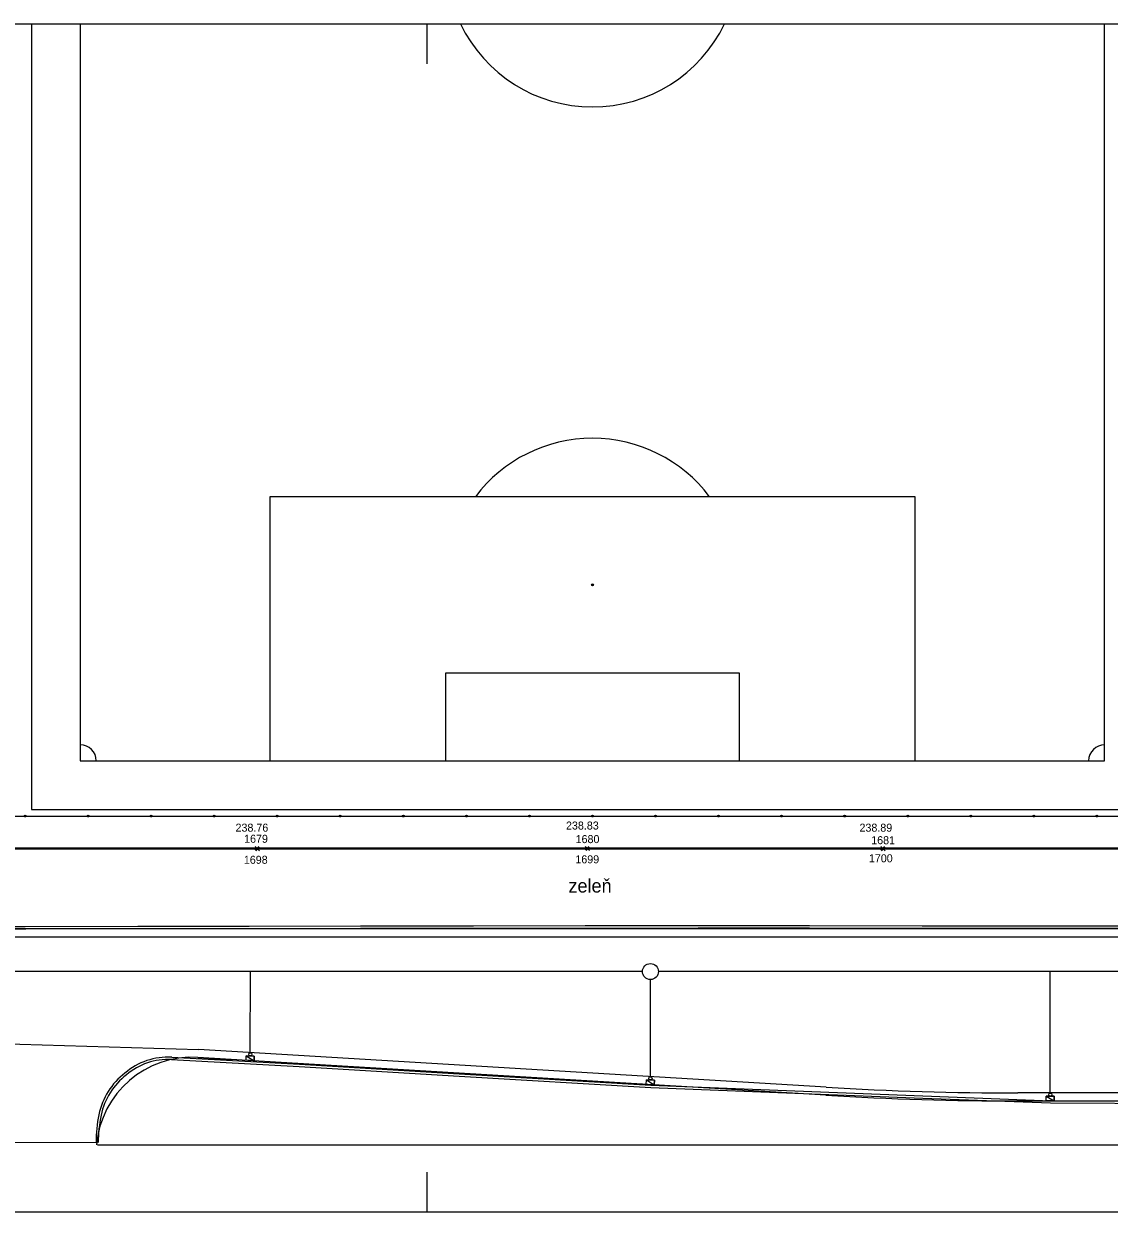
# Model space of a CAD drawing. Extents: x -264165 to -263733, y -1242319 to -1242245.
# Drawn here: x -264043 to -263975.2, y -1242319.2 to -1242244.9 of the extents above; entities that cross this region are included whole.
import ezdxf

# ---------------------------------------------------------------- set-up
doc = ezdxf.new("R2010")
doc.units = 0
for name, color, linetype in [('KFA_BOD_CISLO', 7, 'Continuous'), ('KFA_BOD_SYMBOL', 7, 'Continuous'), ('KFA_BOD_VYSKA', 7, 'Continuous'), ('KFA_SO_20-2_OBRUBNIKY_HORNA_HRANA', 7, 'Continuous'), ('POPIS', 7, 'Continuous'), ('PROJEKT_OBRUBNIKY_KOMUNIKACIE', 7, 'Continuous'), ('PROJEKT_TDZ_VODOROVNE', 7, 'Continuous'), ('RAM_NA_TLAC_1-250', 7, 'Continuous'), ('SITUACIA_DSP_2D', 7, 'Continuous'), ('SO_20-1_OBRUBNIKY_DOLNA_HRANA', 7, 'Continuous'), ('SO_20-1_OBRUBNIKY_DOLNA_HRANA_POMOCNE', 7, 'Continuous'), ('SO_20-1_OBRUBNIKY_HORNA_HRANA', 7, 'Continuous')]:
    doc.layers.add(name, color=color, linetype=linetype)

msp = doc.modelspace()

# ---------------------------------------------------------------- linework, layer by layer
at = {"layer": 'KFA_BOD_SYMBOL'}
for p, q in [((-264028.59, -1242296.556), (-264028.369, -1242296.335)), ((-264028.369, -1242296.556), (-264028.59, -1242296.335)), ((-264028.545, -1242296.597), (-264028.323, -1242296.377)), ((-264028.323, -1242296.597), (-264028.545, -1242296.377)), ((-264007.968, -1242296.552), (-264007.747, -1242296.332)), ((-264007.747, -1242296.552), (-264007.968, -1242296.332)), ((-264007.921, -1242296.595), (-264007.7, -1242296.373)), ((-264007.7, -1242296.595), (-264007.921, -1242296.373)), ((-263989.504, -1242296.561), (-263989.283, -1242296.34)), ((-263989.283, -1242296.561), (-263989.504, -1242296.34)), ((-263989.459, -1242296.603), (-263989.237, -1242296.382)), ((-263989.237, -1242296.603), (-263989.459, -1242296.382))]:
    msp.add_line(p, q, dxfattribs=at)
at = {"layer": 'KFA_SO_20-2_OBRUBNIKY_HORNA_HRANA'}
for points in [[(-264048.312, -1242296.489), (-264028.434, -1242296.487), (-264007.811, -1242296.484), (-263989.348, -1242296.492), (-263970.175, -1242296.491), (-263970.185, -1242293.475)], [(-264048.263, -1242296.44), (-264028.48, -1242296.445), (-264007.857, -1242296.442), (-263989.394, -1242296.45), (-263970.221, -1242296.449), (-263970.229, -1242293.474)]]:
    msp.add_lwpolyline(points, dxfattribs=at)
at = {"layer": 'PROJEKT_OBRUBNIKY_KOMUNIKACIE'}
for p, q in [((-263971.068, -1242301.482), (-264112.961, -1242301.482)), ((-263992.94, -1242311.872), (-264032.171, -1242309.514)), ((-264032.171, -1242309.514), (-264030.1, -1242309.638)), ((-263980.94, -1242312.232), (-263924.192, -1242312.232)), ((-264038.443, -1242314.982), (-263836.403, -1242314.982))]:
    msp.add_line(p, q, dxfattribs=at)
for points in [[(-264042.568, -1242294.032), (-263972.468, -1242294.032), (-263972.468, -1242244.935)], [(-264042.568, -1242244.935), (-264042.568, -1242294.032)], [(-263965.143, -1242296.432), (-264120.018, -1242296.432), (-264120.282, -1242296.432)]]:
    msp.add_lwpolyline(points, dxfattribs=at)
for centre, radius, start, end in [((-264032.531, -1242315.503), 6, 86.56019, 175.02052), ((-263980.94, -1242112.232), 200, 266.56019, 270)]:
    msp.add_arc(centre, radius, start, end, dxfattribs=at)
at = {"layer": 'PROJEKT_TDZ_VODOROVNE'}
for p, q in [((-264112.961, -1242301.982), (-263971.806, -1242301.982)), ((-264050.531, -1242308.482), (-264032.141, -1242309.015)), ((-263992.91, -1242311.373), (-264032.141, -1242309.015)), ((-263842.661, -1242311.732), (-263980.94, -1242311.732))]:
    msp.add_line(p, q, dxfattribs=at)
msp.add_arc((-263980.94, -1242112.232), 199.5, 266.56019, 270, dxfattribs=at)
at = {"layer": 'RAM_NA_TLAC_1-250'}
for p, q in [((-264017.863, -1242244.935), (-264017.863, -1242247.435)), ((-264017.863, -1242316.685), (-264017.863, -1242319.185))]:
    msp.add_line(p, q, dxfattribs=at)
msp.add_lwpolyline([(-264165.363, -1242244.935), (-263732.863, -1242244.935), (-263732.863, -1242319.185), (-264165.363, -1242319.185)], close=True, dxfattribs=at)
at = {"layer": 'SITUACIA_DSP_2D'}
for p, q in [((-264042.568, -1242244.935), (-264042.568, -1242244.935)), ((-264042.568, -1242244.935), (-264042.568, -1242294.032)), ((-264039.518, -1242244.935), (-264039.518, -1242290.982)), ((-263975.518, -1242290.982), (-263975.518, -1242244.935)), ((-263987.358, -1242274.482), (-264027.678, -1242274.482)), ((-264027.678, -1242274.482), (-264027.678, -1242290.982)), ((-263987.358, -1242290.982), (-263987.358, -1242274.482)), ((-264016.678, -1242290.982), (-264016.678, -1242285.482)), ((-264016.678, -1242285.482), (-263998.358, -1242285.482)), ((-263998.358, -1242285.482), (-263998.358, -1242290.982)), ((-264039.518, -1242290.982), (-263975.518, -1242290.982)), ((-264045.118, -1242294.432), (-263972.068, -1242294.432)), ((-264042.908, -1242294.432), (-264043.028, -1242294.432)), ((-264042.968, -1242294.492), (-264042.968, -1242294.372)), ((-264042.568, -1242294.032), (-263972.468, -1242294.032)), ((-264038.969, -1242294.432), (-264039.089, -1242294.432)), ((-264039.029, -1242294.492), (-264039.029, -1242294.372)), ((-264035.03, -1242294.432), (-264035.15, -1242294.432)), ((-264035.09, -1242294.492), (-264035.09, -1242294.372)), ((-264031.091, -1242294.432), (-264031.211, -1242294.432)), ((-264031.151, -1242294.492), (-264031.151, -1242294.372)), ((-264027.152, -1242294.432), (-264027.272, -1242294.432)), ((-264027.212, -1242294.492), (-264027.212, -1242294.372)), ((-264023.213, -1242294.432), (-264023.333, -1242294.432)), ((-264023.273, -1242294.492), (-264023.273, -1242294.372)), ((-264019.274, -1242294.432), (-264019.394, -1242294.432)), ((-264019.334, -1242294.492), (-264019.334, -1242294.372)), ((-264015.336, -1242294.432), (-264015.456, -1242294.432)), ((-264015.396, -1242294.492), (-264015.396, -1242294.372)), ((-264011.397, -1242294.432), (-264011.517, -1242294.432)), ((-264011.457, -1242294.492), (-264011.457, -1242294.372)), ((-264007.458, -1242294.432), (-264007.578, -1242294.432)), ((-264007.518, -1242294.492), (-264007.518, -1242294.372)), ((-264003.519, -1242294.432), (-264003.639, -1242294.432)), ((-264003.579, -1242294.492), (-264003.579, -1242294.372)), ((-263999.58, -1242294.432), (-263999.7, -1242294.432)), ((-263999.64, -1242294.492), (-263999.64, -1242294.372)), ((-263995.641, -1242294.432), (-263995.761, -1242294.432)), ((-263995.701, -1242294.492), (-263995.701, -1242294.372)), ((-263991.702, -1242294.432), (-263991.822, -1242294.432)), ((-263991.762, -1242294.492), (-263991.762, -1242294.372)), ((-263987.763, -1242294.432), (-263987.883, -1242294.432)), ((-263987.823, -1242294.492), (-263987.823, -1242294.372)), ((-263983.824, -1242294.432), (-263983.944, -1242294.432)), ((-263983.884, -1242294.492), (-263983.884, -1242294.372)), ((-263979.886, -1242294.432), (-263980.006, -1242294.432)), ((-263979.946, -1242294.492), (-263979.946, -1242294.372)), ((-263975.947, -1242294.432), (-263976.067, -1242294.432)), ((-263976.007, -1242294.492), (-263976.007, -1242294.372)), ((-263971.068, -1242301.482), (-264112.961, -1242301.482)), ((-264004.396, -1242304.147), (-264044.527, -1242304.147)), ((-264028.895, -1242309.22), (-264028.89, -1242304.147)), ((-263954.413, -1242304.147), (-264003.396, -1242304.147)), ((-263978.913, -1242311.742), (-263978.913, -1242304.147)), ((-264003.896, -1242310.723), (-264003.896, -1242304.647)), ((-264029.162, -1242309.695), (-264029.144, -1242309.405)), ((-264029.144, -1242309.405), (-264028.645, -1242309.435)), ((-264029.144, -1242309.405), (-264028.663, -1242309.725)), ((-264029.144, -1242309.405), (-264028.663, -1242309.725)), ((-264028.645, -1242309.435), (-264029.144, -1242309.405)), ((-263992.94, -1242311.872), (-264032.171, -1242309.514)), ((-264032.171, -1242309.514), (-264032.171, -1242309.514)), ((-264028.663, -1242309.725), (-264029.162, -1242309.695)), ((-264028.645, -1242309.435), (-264028.663, -1242309.725)), ((-264028.663, -1242309.725), (-264028.645, -1242309.435)), ((-264004.163, -1242311.197), (-264004.146, -1242310.908)), ((-264003.664, -1242311.227), (-264004.163, -1242311.197)), ((-264004.146, -1242310.908), (-264003.646, -1242310.938)), ((-264004.146, -1242310.908), (-264003.664, -1242311.227)), ((-264004.146, -1242310.908), (-264003.664, -1242311.227)), ((-264003.646, -1242310.938), (-264004.146, -1242310.908)), ((-264003.646, -1242310.938), (-264003.664, -1242311.227)), ((-264003.664, -1242311.227), (-264003.646, -1242310.938)), ((-263980.94, -1242312.232), (-263857.327, -1242312.232)), ((-263979.163, -1242311.942), (-263978.663, -1242311.942)), ((-263979.163, -1242312.232), (-263979.163, -1242311.942)), ((-263979.163, -1242311.942), (-263978.663, -1242312.232)), ((-263979.163, -1242311.942), (-263978.663, -1242312.232)), ((-263978.663, -1242311.942), (-263979.163, -1242311.942)), ((-263978.663, -1242312.232), (-263979.163, -1242312.232)), ((-263978.663, -1242311.942), (-263978.663, -1242312.232)), ((-263978.663, -1242312.232), (-263978.663, -1242311.942)), ((-264038.443, -1242314.982), (-263836.403, -1242314.982))]:
    msp.add_line(p, q, dxfattribs=at)
msp.add_lwpolyline([(-263965.143, -1242296.432), (-264120.018, -1242296.432), (-264120.282, -1242296.432)], dxfattribs=at)
for centre, radius in [((-264007.518, -1242279.982), 0.06), ((-264042.968, -1242294.432), 0.06), ((-264039.029, -1242294.432), 0.06), ((-264035.09, -1242294.432), 0.06), ((-264031.151, -1242294.432), 0.06), ((-264027.212, -1242294.432), 0.06), ((-264023.273, -1242294.432), 0.06), ((-264019.334, -1242294.432), 0.06), ((-264015.396, -1242294.432), 0.06), ((-264011.457, -1242294.432), 0.06), ((-264007.518, -1242294.432), 0.06), ((-264003.579, -1242294.432), 0.06), ((-263999.64, -1242294.432), 0.06), ((-263995.701, -1242294.432), 0.06), ((-263991.762, -1242294.432), 0.06), ((-263987.823, -1242294.432), 0.06), ((-263983.884, -1242294.432), 0.06), ((-263979.946, -1242294.432), 0.06), ((-263976.007, -1242294.432), 0.06), ((-264003.896, -1242304.147), 0.5), ((-264028.895, -1242309.32), 0.1), ((-264003.896, -1242310.823), 0.1), ((-263978.913, -1242311.842), 0.1)]:
    msp.add_circle(centre, radius, dxfattribs=at)
for centre, radius, start, end in [((-264007.518, -1242240.982), 9.15, 205.59455, 334.40545), ((-264007.518, -1242279.982), 9.15, 36.94821, 143.05179), ((-264007.518, -1242279.982), 0.0303, 90, 270), ((-264007.518, -1242279.982), 0.0303, 270, 90), ((-264039.518, -1242290.982), 1, 0, 90), ((-263975.518, -1242290.982), 1, 90, 180), ((-264032.531, -1242315.503), 6, 86.56019, 175.02052), ((-263980.94, -1242112.232), 200, 266.56019, 270)]:
    msp.add_arc(centre, radius, start, end, dxfattribs=at)
at = {"layer": 'SO_20-1_OBRUBNIKY_DOLNA_HRANA'}
for points in [[(-264084.992, -1242301.468), (-264078.002, -1242301.482), (-264070.986, -1242301.489), (-264064.021, -1242301.482), (-264056.978, -1242301.482), (-264049.977, -1242301.481), (-264042.921, -1242301.475), (-264035.92, -1242301.469), (-264028.972, -1242301.456), (-264022.003, -1242301.442), (-264014.974, -1242301.438), (-264007.969, -1242301.429), (-264000.909, -1242301.426), (-263993.952, -1242301.425)], [(-263993.952, -1242301.425), (-263986.921, -1242301.437), (-263979.924, -1242301.441), (-263972.919, -1242301.445), (-263970.912, -1242301.438)], [(-264033.805, -1242309.499), (-264025.829, -1242309.934), (-264015.848, -1242310.539), (-264003.863, -1242311.243), (-263994.874, -1242311.606), (-263986.882, -1242311.907), (-263978.856, -1242312.215), (-263970.892, -1242312.243), (-263962.891, -1242312.248), (-263954.893, -1242312.255), (-263953.892, -1242312.266), (-263946.9, -1242312.261), (-263936.904, -1242312.253), (-263927.909, -1242312.236)]]:
    msp.add_lwpolyline(points, dxfattribs=at)
for centre, major_axis, ratio, start_param, end_param in [((-264034.026, -1242313.661), (0.481, 4.14), 0.999833, 0.062646, 0.82187), ((-264034.01, -1242313.997), (-3.876, -2.174), 0.998598, 4.860749, 5.565783), ((-264031.337, -1242314.585), (-3.403, -6.376), 0.992668, 4.990922, 5.232731)]:
    msp.add_ellipse(centre, major_axis=major_axis, ratio=ratio, start_param=start_param, end_param=end_param, dxfattribs=at)
at = {"layer": 'SO_20-1_OBRUBNIKY_DOLNA_HRANA_POMOCNE'}
msp.add_line((-264044.462, -1242314.814), (-264038.521, -1242314.824), dxfattribs=at)
at = {"layer": 'SO_20-1_OBRUBNIKY_HORNA_HRANA'}
for points in [[(-264084.994, -1242301.327), (-264077.993, -1242301.335), (-264070.958, -1242301.339), (-264063.998, -1242301.345), (-264056.974, -1242301.334), (-264049.976, -1242301.332), (-264042.963, -1242301.324), (-264035.917, -1242301.32), (-264028.967, -1242301.31), (-264022.019, -1242301.3), (-264014.954, -1242301.285), (-264007.975, -1242301.28), (-264000.942, -1242301.277), (-263993.949, -1242301.276)], [(-263993.949, -1242301.276), (-263986.923, -1242301.287), (-263979.923, -1242301.293), (-263972.92, -1242301.295), (-263970.913, -1242301.29)], [(-264033.819, -1242309.643), (-264025.833, -1242310.082), (-264015.854, -1242310.687), (-264003.872, -1242311.39), (-263994.881, -1242311.753), (-263986.886, -1242312.056), (-263978.896, -1242312.359), (-263970.883, -1242312.387), (-263962.888, -1242312.396), (-263954.878, -1242312.403), (-263953.896, -1242312.41), (-263946.895, -1242312.406), (-263936.899, -1242312.396), (-263927.906, -1242312.382)]]:
    msp.add_lwpolyline(points, dxfattribs=at)
for centre, major_axis, ratio, start_param, end_param in [((-264034.033, -1242313.625), (-1.327, 3.76), 0.99987, 5.8902, 6.655533), ((-264034.073, -1242313.959), (-3.712, -2.023), 0.998497, 4.865889, 5.584759), ((-264033.999, -1242314.008), (-1.241, -6.235), 0.677566, 4.705598, 4.976492)]:
    msp.add_ellipse(centre, major_axis=major_axis, ratio=ratio, start_param=start_param, end_param=end_param, dxfattribs=at)

# ---------------------------------------------------------------- texts
at = {"layer": 'KFA_BOD_CISLO'}
for s, p in [('1679', (-264029.282, -1242296.102)), ('1680', (-264008.571, -1242296.124)), ('1681', (-263990.103, -1242296.193)), ('1698', (-264029.298, -1242297.415)), ('1699', (-264008.587, -1242297.386)), ('1700', (-263990.248, -1242297.322))]:
    msp.add_text(s, height=0.5, dxfattribs=at).set_placement(p)
at = {"layer": 'KFA_BOD_VYSKA'}
for s, p in [('238.76', (-264029.817, -1242295.409)), ('238.83', (-264009.172, -1242295.276)), ('238.89', (-263990.836, -1242295.41))]:
    msp.add_text(s, height=0.5, dxfattribs=at).set_placement(p)
at = {"layer": 'POPIS'}
msp.add_text('zeleň', height=0.8438, dxfattribs=at).set_placement((-264009.018, -1242299.211))

doc.saveas('drawing.dxf')
